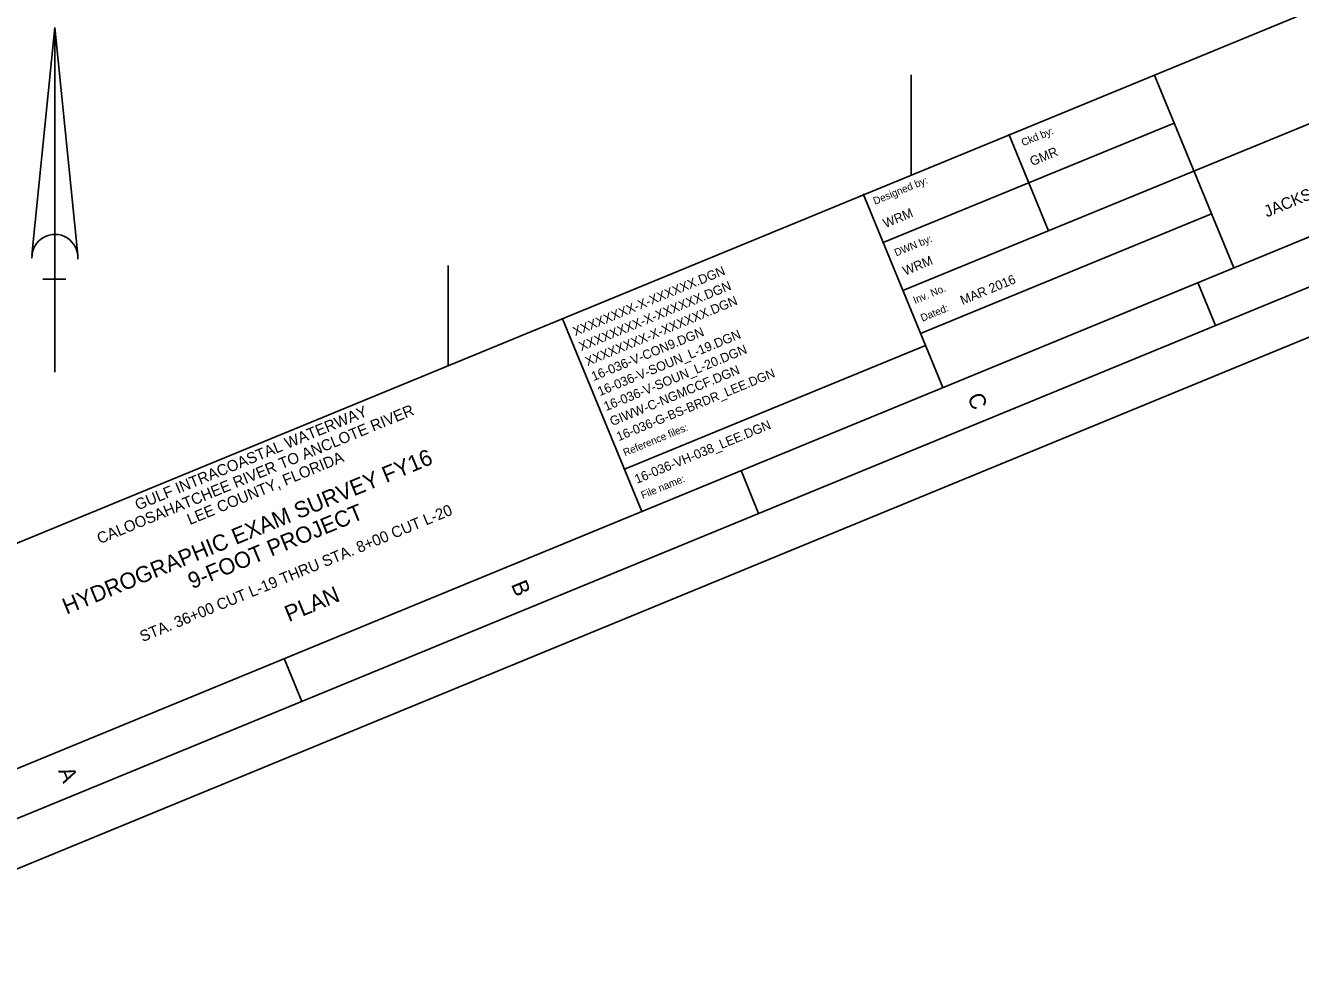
# Model space of a CAD drawing. Extents: x 579601 to 584420, y 852483 to 857846.
# Drawn here: x 581544 to 582920, y 852483 to 853500 of the extents above; entities that cross this region are included whole.
import ezdxf

# ---------------------------------------------------------------- set-up
doc = ezdxf.new("R2010")
doc.units = 0
for name, color, linetype in [('G-ANNO-NPLT', 7, 'Continuous'), ('G-ANNO-TEXT-DRWG', 7, 'Continuous'), ('G-ANNO-TEXT-PROJ', 7, 'Continuous'), ('G-ANNO-TEXT-TTLB', 7, 'Continuous'), ('G-ANNO-TTLB', 7, 'Continuous'), ('V-ANNO-SYMB', 7, 'Continuous'), ('V-TOPO-COOR-STAT', 7, 'Continuous')]:
    doc.layers.add(name, color=color, linetype=linetype)

msp = doc.modelspace()

# ---------------------------------------------------------------- linework, layer by layer
at = {"layer": 'G-ANNO-NPLT'}
msp.add_lwpolyline([(582745.7, 857846.1), (584419.8, 853777), (581275.5, 852483.4), (579601.4, 856552.5)], close=True, dxfattribs=at)
at = {"layer": 'G-ANNO-TTLB'}
for p, q in [((584203.6, 854039.5), (581244.3, 852822)), ((582491.1, 853214), (583286.2, 853540.4)), ((582762.3, 853447.4), (582848.3, 853238.6)), ((582469.8, 853265.8), (582784, 853394.7)), ((582605.3, 853382.8), (582648.2, 853278.5)), ((582448.1, 853318.6), (582534.1, 853109.3)), ((582824.3, 853296.8), (582510.2, 853167.6)), ((582828.5, 853176.4), (582809.5, 853222.6)), ((582123.6, 853183.7), (582209.2, 852975.7)), ((582515.4, 853154.9), (582190.4, 853021.2)), ((582335.3, 852973.5), (582316.3, 853019.7)), ((581842.1, 852770.6), (581823.1, 852816.8))]:
    msp.add_line(p, q, dxfattribs=at)
for points in [[(579666.7, 856525.2), (581302.7, 852548.7), (584354.5, 853804.2), (582718.5, 857780.8)], [(584289.2, 853831.4), (582719.8, 857646.2), (579760.5, 856428.7), (581329.9, 852613.9)]]:
    msp.add_lwpolyline(points, close=True, dxfattribs=at)
at = {"layer": 'V-ANNO-SYMB'}
for p, q in [((581550.7, 853252.4), (581575.4, 853498.1)), ((581575.4, 853125.8), (581575.4, 853498.1)), ((581600.1, 853252.4), (581575.4, 853498.1)), ((581587.2, 853226.3), (581562.3, 853226.3))]:
    msp.add_line(p, q, dxfattribs=at)
msp.add_arc((581575.4, 853249.9), 24.8, 355.2984, 182.0673, dxfattribs=at)
at = {"layer": 'V-TOPO-COOR-STAT'}
for p, q in [((582500, 853338.6), (582500, 853446.8)), ((582000, 853132.9), (582000, 853241.1))]:
    msp.add_line(p, q, dxfattribs=at)

# ---------------------------------------------------------------- texts
at = {"layer": 'G-ANNO-TEXT-DRWG'}
for s, height, p in [('GMR', 10, (582630.6, 853348.3)), ('WRM', 10, (582472.1, 853281.4)), ('WRM', 10, (582493.4, 853230.1)), ('XXXXXXXX-X-XXXXXX.DGN', 10, (582137.2, 853164.7)), ('XXXXXXXX-X-XXXXXX.DGN', 10, (582143.8, 853148.5)), ('XXXXXXXX-X-XXXXXX.DGN', 10, (582150.5, 853132.4)), ('16-036-V-CON9.DGN', 10, (582157.1, 853116.2)), ('16-036-V-SOUN_L-19.DGN', 10, (582163.8, 853100)), ('16-036-V-SOUN_L-20.DGN', 10, (582170.5, 853083.8)), ('GIWW-C-NGMCCF.DGN', 10, (582177.1, 853067.6)), ('16-036-VH-038_LEE.DGN', 10, (582203.8, 853005.4)), ('STA. 36+00 CUT L-19 THRU STA. 8+00 CUT L-20', 12, (581670.1, 852834.5)), ('PLAN', 17.5, (581828, 852856.1))]:
    msp.add_text(s, height=height, rotation=22.363, dxfattribs=at).set_placement(p)
at = {"layer": 'G-ANNO-TEXT-PROJ'}
for s, height, p in [('MAR 2016', 10, (582555.4, 853198.4)), ('16-036-G-BS-BRDR_LEE.DGN', 9.8, (582184.2, 853051.4)), ('CALOOSAHATCHEE RIVER TO ANCLOTE RIVER', 12, (581623.9, 852940.3)), ('GULF INTRACOASTAL WATERWAY', 12, (581664.9, 852976.6)), ('HYDROGRAPHIC EXAM SURVEY FY16', 17.5, (581588, 852864.2)), ('LEE COUNTY, FLORIDA', 12, (581721.2, 852960.9)), ('9-FOOT PROJECT', 17.5, (581723.6, 852891.6))]:
    msp.add_text(s, height=height, rotation=22.363, dxfattribs=at).set_placement(p)
at = {"layer": 'G-ANNO-TEXT-TTLB'}
for s, height, p in [('JACKSONVILLE DISTRICT, CORPS OF ENGINEERS', 12.5, (582884, 853292.9)), ('Ckd by:', 8, (582620.9, 853369.7)), ('Designed by:', 8, (582460.9, 853306.5)), ('DWN by:', 8, (582483.8, 853250.8)), ('Inv. No.', 8, (582504.1, 853199.5)), ('Dated:', 8, (582512.1, 853180.3)), ('Reference files:', 8, (582191, 853035.1)), ('File name:', 8, (582210.2, 852989))]:
    msp.add_text(s, height=height, rotation=22.363, dxfattribs=at).set_placement(p)
at = {"layer": 'G-ANNO-TTLB'}
for s, p in [('C', (582560.3, 853099.3)), ('B', (582067.7, 852896.9)), ('A', (581578.7, 852695.7))]:
    msp.add_text(s, height=17.5, rotation=292.363, dxfattribs=at).set_placement(p)

doc.saveas('drawing.dxf')
